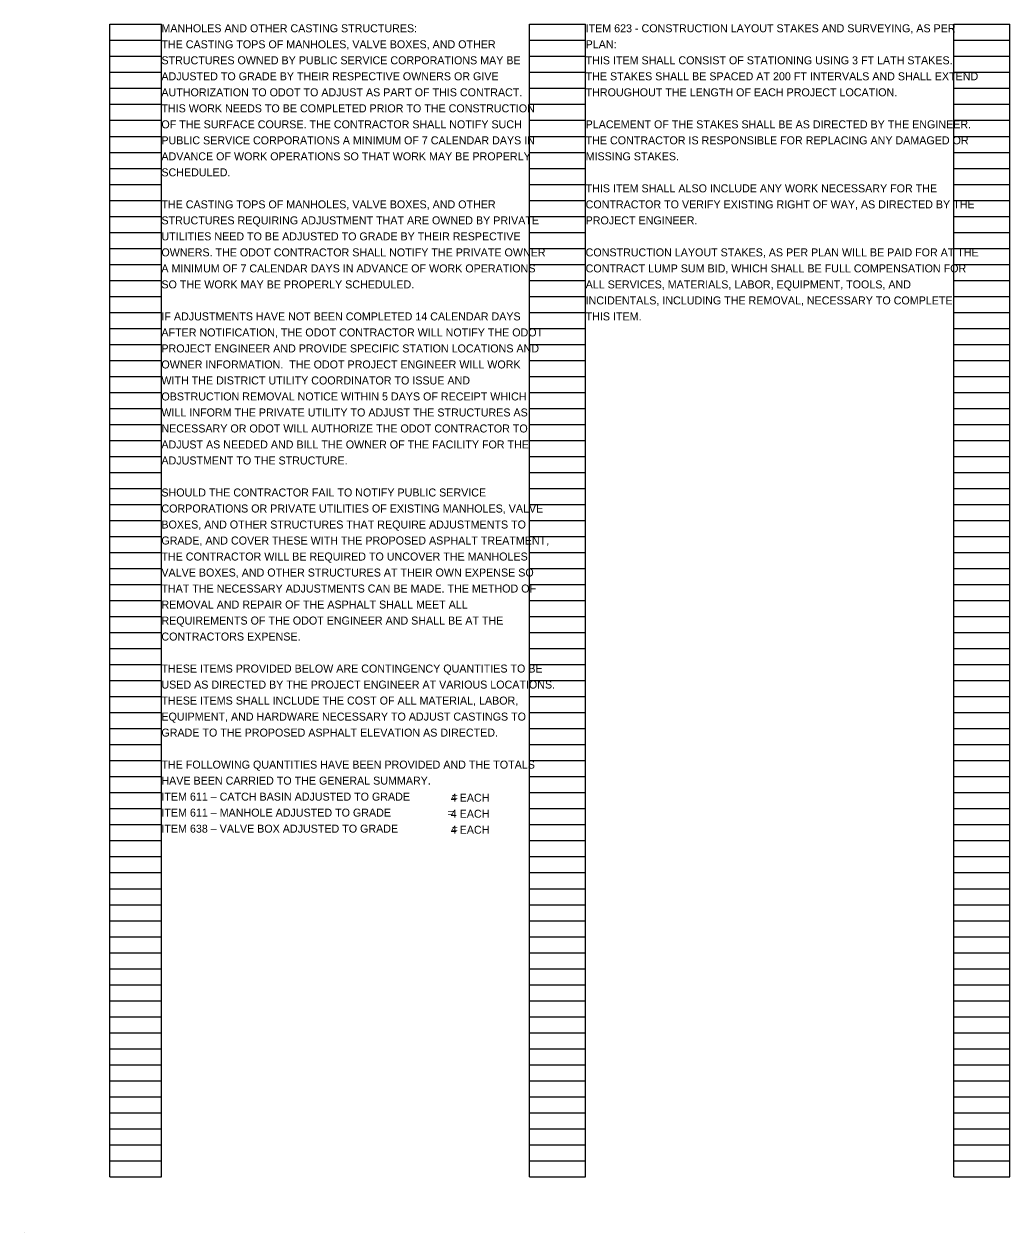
# Model space of a CAD drawing. Extents: x 28776.5 to 28808.5, y 9178.8 to 9230.7.
# Drawn here: x 28776.53 to 28793.77, y 9178.8 to 9199.94 of the extents above; entities that cross this region are included whole.
import ezdxf

# ---------------------------------------------------------------- set-up
doc = ezdxf.new("R2010")
doc.units = 0
doc.layers.add('SH_Data', color=7, linetype='Continuous')
doc.layers.add('SH_Text', color=7, linetype='Continuous')

msp = doc.modelspace()

# ---------------------------------------------------------------- linework, layer by layer
at = {"layer": 'SH_Data'}
for p, q in [((28778.029, 9179.776), (28778.029, 9199.936)), ((28778.029, 9199.936), (28778.929, 9199.936)), ((28778.929, 9179.776), (28778.929, 9199.936)), ((28785.369, 9179.776), (28785.369, 9199.936)), ((28785.369, 9199.936), (28786.349, 9199.936)), ((28786.349, 9179.776), (28786.349, 9199.936)), ((28792.789, 9179.776), (28792.789, 9199.936)), ((28792.789, 9199.936), (28793.769, 9199.936)), ((28793.769, 9179.776), (28793.769, 9199.936)), ((28778.029, 9199.656), (28778.929, 9199.656)), ((28785.369, 9199.656), (28786.349, 9199.656)), ((28792.789, 9199.656), (28793.769, 9199.656)), ((28778.029, 9199.376), (28778.929, 9199.376)), ((28785.369, 9199.376), (28786.349, 9199.376)), ((28792.789, 9199.376), (28793.769, 9199.376)), ((28778.029, 9199.096), (28778.929, 9199.096)), ((28785.369, 9199.096), (28786.349, 9199.096)), ((28792.789, 9199.096), (28793.769, 9199.096)), ((28778.029, 9198.816), (28778.929, 9198.816)), ((28785.369, 9198.816), (28786.349, 9198.816)), ((28792.789, 9198.816), (28793.769, 9198.816)), ((28778.029, 9198.536), (28778.929, 9198.536)), ((28785.369, 9198.536), (28786.349, 9198.536)), ((28792.789, 9198.536), (28793.769, 9198.536)), ((28778.029, 9198.256), (28778.929, 9198.256)), ((28785.369, 9198.256), (28786.349, 9198.256)), ((28792.789, 9198.256), (28793.769, 9198.256)), ((28778.029, 9197.976), (28778.929, 9197.976)), ((28785.369, 9197.976), (28786.349, 9197.976)), ((28792.789, 9197.976), (28793.769, 9197.976)), ((28778.029, 9197.696), (28778.929, 9197.696)), ((28785.369, 9197.696), (28786.349, 9197.696)), ((28792.789, 9197.696), (28793.769, 9197.696)), ((28778.029, 9197.416), (28778.929, 9197.416)), ((28785.369, 9197.416), (28786.349, 9197.416)), ((28792.789, 9197.416), (28793.769, 9197.416)), ((28778.029, 9197.136), (28778.929, 9197.136)), ((28785.369, 9197.136), (28786.349, 9197.136)), ((28792.789, 9197.136), (28793.769, 9197.136)), ((28778.029, 9196.856), (28778.929, 9196.856)), ((28785.369, 9196.856), (28786.349, 9196.856)), ((28792.789, 9196.856), (28793.769, 9196.856)), ((28778.029, 9196.576), (28778.929, 9196.576)), ((28785.369, 9196.576), (28786.349, 9196.576)), ((28792.789, 9196.576), (28793.769, 9196.576)), ((28778.029, 9196.296), (28778.929, 9196.296)), ((28785.369, 9196.296), (28786.349, 9196.296)), ((28792.789, 9196.296), (28793.769, 9196.296)), ((28778.029, 9196.016), (28778.929, 9196.016)), ((28785.369, 9196.016), (28786.349, 9196.016)), ((28792.789, 9196.016), (28793.769, 9196.016)), ((28778.029, 9195.736), (28778.929, 9195.736)), ((28785.369, 9195.736), (28786.349, 9195.736)), ((28792.789, 9195.736), (28793.769, 9195.736)), ((28778.029, 9195.456), (28778.929, 9195.456)), ((28785.369, 9195.456), (28786.349, 9195.456)), ((28792.789, 9195.456), (28793.769, 9195.456)), ((28778.029, 9195.176), (28778.929, 9195.176)), ((28785.369, 9195.176), (28786.349, 9195.176)), ((28792.789, 9195.176), (28793.769, 9195.176)), ((28778.029, 9194.896), (28778.929, 9194.896)), ((28785.369, 9194.896), (28786.349, 9194.896)), ((28792.789, 9194.896), (28793.769, 9194.896)), ((28778.029, 9194.616), (28778.929, 9194.616)), ((28785.369, 9194.616), (28786.349, 9194.616)), ((28792.789, 9194.616), (28793.769, 9194.616)), ((28778.029, 9194.336), (28778.929, 9194.336)), ((28785.369, 9194.336), (28786.349, 9194.336)), ((28792.789, 9194.336), (28793.769, 9194.336)), ((28778.029, 9194.056), (28778.929, 9194.056)), ((28785.369, 9194.056), (28786.349, 9194.056)), ((28792.789, 9194.056), (28793.769, 9194.056)), ((28778.029, 9193.776), (28778.929, 9193.776)), ((28785.369, 9193.776), (28786.349, 9193.776)), ((28792.789, 9193.776), (28793.769, 9193.776)), ((28778.029, 9193.496), (28778.929, 9193.496)), ((28785.369, 9193.496), (28786.349, 9193.496)), ((28792.789, 9193.496), (28793.769, 9193.496)), ((28778.029, 9193.216), (28778.929, 9193.216)), ((28785.369, 9193.216), (28786.349, 9193.216)), ((28792.789, 9193.216), (28793.769, 9193.216)), ((28778.029, 9192.936), (28778.929, 9192.936)), ((28785.369, 9192.936), (28786.349, 9192.936)), ((28792.789, 9192.936), (28793.769, 9192.936)), ((28778.029, 9192.656), (28778.929, 9192.656)), ((28785.369, 9192.656), (28786.349, 9192.656)), ((28792.789, 9192.656), (28793.769, 9192.656)), ((28778.029, 9192.376), (28778.929, 9192.376)), ((28785.369, 9192.376), (28786.349, 9192.376)), ((28792.789, 9192.376), (28793.769, 9192.376)), ((28778.029, 9192.096), (28778.929, 9192.096)), ((28785.369, 9192.096), (28786.349, 9192.096)), ((28792.789, 9192.096), (28793.769, 9192.096)), ((28778.029, 9191.816), (28778.929, 9191.816)), ((28785.369, 9191.816), (28786.349, 9191.816)), ((28792.789, 9191.816), (28793.769, 9191.816)), ((28778.029, 9191.536), (28778.929, 9191.536)), ((28785.369, 9191.536), (28786.349, 9191.536)), ((28792.789, 9191.536), (28793.769, 9191.536)), ((28778.029, 9191.256), (28778.929, 9191.256)), ((28785.369, 9191.256), (28786.349, 9191.256)), ((28792.789, 9191.256), (28793.769, 9191.256)), ((28778.029, 9190.976), (28778.929, 9190.976)), ((28785.369, 9190.976), (28786.349, 9190.976)), ((28792.789, 9190.976), (28793.769, 9190.976)), ((28778.029, 9190.696), (28778.929, 9190.696)), ((28785.369, 9190.696), (28786.349, 9190.696)), ((28792.789, 9190.696), (28793.769, 9190.696)), ((28778.029, 9190.416), (28778.929, 9190.416)), ((28785.369, 9190.416), (28786.349, 9190.416)), ((28792.789, 9190.416), (28793.769, 9190.416)), ((28778.029, 9190.136), (28778.929, 9190.136)), ((28785.369, 9190.136), (28786.349, 9190.136)), ((28792.789, 9190.136), (28793.769, 9190.136)), ((28778.029, 9189.856), (28778.929, 9189.856)), ((28785.369, 9189.856), (28786.349, 9189.856)), ((28792.789, 9189.856), (28793.769, 9189.856)), ((28778.029, 9189.576), (28778.929, 9189.576)), ((28785.369, 9189.576), (28786.349, 9189.576)), ((28792.789, 9189.576), (28793.769, 9189.576)), ((28778.029, 9189.296), (28778.929, 9189.296)), ((28785.369, 9189.296), (28786.349, 9189.296)), ((28792.789, 9189.296), (28793.769, 9189.296)), ((28778.029, 9189.016), (28778.929, 9189.016)), ((28785.369, 9189.016), (28786.349, 9189.016)), ((28792.789, 9189.016), (28793.769, 9189.016)), ((28778.029, 9188.736), (28778.929, 9188.736)), ((28785.369, 9188.736), (28786.349, 9188.736)), ((28792.789, 9188.736), (28793.769, 9188.736)), ((28778.029, 9188.456), (28778.929, 9188.456)), ((28785.369, 9188.456), (28786.349, 9188.456)), ((28792.789, 9188.456), (28793.769, 9188.456)), ((28778.029, 9188.176), (28778.929, 9188.176)), ((28785.369, 9188.176), (28786.349, 9188.176)), ((28792.789, 9188.176), (28793.769, 9188.176)), ((28778.029, 9187.896), (28778.929, 9187.896)), ((28785.369, 9187.896), (28786.349, 9187.896)), ((28792.789, 9187.896), (28793.769, 9187.896)), ((28778.029, 9187.616), (28778.929, 9187.616)), ((28785.369, 9187.616), (28786.349, 9187.616)), ((28792.789, 9187.616), (28793.769, 9187.616)), ((28778.029, 9187.336), (28778.929, 9187.336)), ((28785.369, 9187.336), (28786.349, 9187.336)), ((28792.789, 9187.336), (28793.769, 9187.336)), ((28778.029, 9187.056), (28778.929, 9187.056)), ((28785.369, 9187.056), (28786.349, 9187.056)), ((28792.789, 9187.056), (28793.769, 9187.056)), ((28778.029, 9186.776), (28778.929, 9186.776)), ((28785.369, 9186.776), (28786.349, 9186.776)), ((28792.789, 9186.776), (28793.769, 9186.776)), ((28778.029, 9186.496), (28778.929, 9186.496)), ((28785.369, 9186.496), (28786.349, 9186.496)), ((28792.789, 9186.496), (28793.769, 9186.496)), ((28778.029, 9186.216), (28778.929, 9186.216)), ((28785.369, 9186.216), (28786.349, 9186.216)), ((28792.789, 9186.216), (28793.769, 9186.216)), ((28778.029, 9185.936), (28778.929, 9185.936)), ((28785.369, 9185.936), (28786.349, 9185.936)), ((28792.789, 9185.936), (28793.769, 9185.936)), ((28778.029, 9185.656), (28778.929, 9185.656)), ((28785.369, 9185.656), (28786.349, 9185.656)), ((28792.789, 9185.656), (28793.769, 9185.656)), ((28778.029, 9185.376), (28778.929, 9185.376)), ((28785.369, 9185.376), (28786.349, 9185.376)), ((28792.789, 9185.376), (28793.769, 9185.376)), ((28778.029, 9185.096), (28778.929, 9185.096)), ((28785.369, 9185.096), (28786.349, 9185.096)), ((28792.789, 9185.096), (28793.769, 9185.096)), ((28778.029, 9184.816), (28778.929, 9184.816)), ((28785.369, 9184.816), (28786.349, 9184.816)), ((28792.789, 9184.816), (28793.769, 9184.816)), ((28778.029, 9184.536), (28778.929, 9184.536)), ((28785.369, 9184.536), (28786.349, 9184.536)), ((28792.789, 9184.536), (28793.769, 9184.536)), ((28778.029, 9184.256), (28778.929, 9184.256)), ((28785.369, 9184.256), (28786.349, 9184.256)), ((28792.789, 9184.256), (28793.769, 9184.256)), ((28778.029, 9183.976), (28778.929, 9183.976)), ((28785.369, 9183.976), (28786.349, 9183.976)), ((28792.789, 9183.976), (28793.769, 9183.976)), ((28778.029, 9183.696), (28778.929, 9183.696)), ((28785.369, 9183.696), (28786.349, 9183.696)), ((28792.789, 9183.696), (28793.769, 9183.696)), ((28778.029, 9183.416), (28778.929, 9183.416)), ((28785.369, 9183.416), (28786.349, 9183.416)), ((28792.789, 9183.416), (28793.769, 9183.416)), ((28778.029, 9183.136), (28778.929, 9183.136)), ((28785.369, 9183.136), (28786.349, 9183.136)), ((28792.789, 9183.136), (28793.769, 9183.136)), ((28778.029, 9182.856), (28778.929, 9182.856)), ((28785.369, 9182.856), (28786.349, 9182.856)), ((28792.789, 9182.856), (28793.769, 9182.856)), ((28778.029, 9182.576), (28778.929, 9182.576)), ((28785.369, 9182.576), (28786.349, 9182.576)), ((28792.789, 9182.576), (28793.769, 9182.576)), ((28778.029, 9182.296), (28778.929, 9182.296)), ((28785.369, 9182.296), (28786.349, 9182.296)), ((28792.789, 9182.296), (28793.769, 9182.296)), ((28778.029, 9182.016), (28778.929, 9182.016)), ((28785.369, 9182.016), (28786.349, 9182.016)), ((28792.789, 9182.016), (28793.769, 9182.016)), ((28778.029, 9181.736), (28778.929, 9181.736)), ((28785.369, 9181.736), (28786.349, 9181.736)), ((28792.789, 9181.736), (28793.769, 9181.736)), ((28778.029, 9181.456), (28778.929, 9181.456)), ((28785.369, 9181.456), (28786.349, 9181.456)), ((28792.789, 9181.456), (28793.769, 9181.456)), ((28778.029, 9181.176), (28778.929, 9181.176)), ((28785.369, 9181.176), (28786.349, 9181.176)), ((28792.789, 9181.176), (28793.769, 9181.176)), ((28778.029, 9180.896), (28778.929, 9180.896)), ((28785.369, 9180.896), (28786.349, 9180.896)), ((28792.789, 9180.896), (28793.769, 9180.896)), ((28778.029, 9180.616), (28778.929, 9180.616)), ((28785.369, 9180.616), (28786.349, 9180.616)), ((28792.789, 9180.616), (28793.769, 9180.616)), ((28778.029, 9180.336), (28778.929, 9180.336)), ((28785.369, 9180.336), (28786.349, 9180.336)), ((28792.789, 9180.336), (28793.769, 9180.336)), ((28778.029, 9180.056), (28778.929, 9180.056)), ((28785.369, 9180.056), (28786.349, 9180.056)), ((28792.789, 9180.056), (28793.769, 9180.056)), ((28778.029, 9179.776), (28778.929, 9179.776)), ((28785.369, 9179.776), (28786.349, 9179.776)), ((28792.789, 9179.776), (28793.769, 9179.776)), ((28776.529, 9178.796), (28776.529, 9178.796))]:
    msp.add_line(p, q, dxfattribs=at)

# ---------------------------------------------------------------- texts
for p in [(28783.99, 9186.337), (28783.99, 9186.057), (28783.99, 9185.777)]:
    msp.add_text('4 EACH', height=0.14, dxfattribs=at).set_placement(p)
at = {"layer": 'SH_Text'}
for s, p in [('MANHOLES AND OTHER CASTING STRUCTURES:', (28778.929, 9199.796)), ('ITEM 623 - CONSTRUCTION LAYOUT STAKES AND SURVEYING, AS PER ', (28786.349, 9199.796)), ('THE CASTING TOPS OF MANHOLES, VALVE BOXES, AND OTHER ', (28778.929, 9199.516)), ('PLAN:', (28786.349, 9199.516)), ('STRUCTURES OWNED BY PUBLIC SERVICE CORPORATIONS MAY BE ', (28778.929, 9199.236)), ('THIS ITEM SHALL CONSIST OF STATIONING USING 3 FT LATH STAKES. ', (28786.349, 9199.236)), ('ADJUSTED TO GRADE BY THEIR RESPECTIVE OWNERS OR GIVE ', (28778.929, 9198.956)), ('THE STAKES SHALL BE SPACED AT 200 FT INTERVALS AND SHALL EXTEND ', (28786.349, 9198.956)), ('AUTHORIZATION TO ODOT TO ADJUST AS PART OF THIS CONTRACT.  ', (28778.929, 9198.676)), ('THROUGHOUT THE LENGTH OF EACH PROJECT LOCATION.', (28786.349, 9198.676)), ('THIS WORK NEEDS TO BE COMPLETED PRIOR TO THE CONSTRUCTION ', (28778.929, 9198.396)), ('OF THE SURFACE COURSE. THE CONTRACTOR SHALL NOTIFY SUCH ', (28778.929, 9198.116)), ('PLACEMENT OF THE STAKES SHALL BE AS DIRECTED BY THE ENGINEER. ', (28786.349, 9198.116)), ('PUBLIC SERVICE CORPORATIONS A MINIMUM OF 7 CALENDAR DAYS IN ', (28778.929, 9197.836)), ('THE CONTRACTOR IS RESPONSIBLE FOR REPLACING ANY DAMAGED OR ', (28786.349, 9197.836)), ('ADVANCE OF WORK OPERATIONS SO THAT WORK MAY BE PROPERLY ', (28778.929, 9197.556)), ('MISSING STAKES.', (28786.349, 9197.556)), ('SCHEDULED.', (28778.929, 9197.276)), ('THIS ITEM SHALL ALSO INCLUDE ANY WORK NECESSARY FOR THE ', (28786.349, 9196.996)), ('THE CASTING TOPS OF MANHOLES, VALVE BOXES, AND OTHER ', (28778.929, 9196.716)), ('CONTRACTOR TO VERIFY EXISTING RIGHT OF WAY, AS DIRECTED BY THE ', (28786.349, 9196.716)), ('STRUCTURES REQUIRING ADJUSTMENT THAT ARE OWNED BY PRIVATE ', (28778.929, 9196.436)), ('PROJECT ENGINEER. ', (28786.349, 9196.436)), ('UTILITIES NEED TO BE ADJUSTED TO GRADE BY THEIR RESPECTIVE ', (28778.929, 9196.156)), ('OWNERS. THE ODOT CONTRACTOR SHALL NOTIFY THE PRIVATE OWNER ', (28778.929, 9195.876)), ('CONSTRUCTION LAYOUT STAKES, AS PER PLAN WILL BE PAID FOR AT THE ', (28786.349, 9195.876)), ('A MINIMUM OF 7 CALENDAR DAYS IN ADVANCE OF WORK OPERATIONS ', (28778.929, 9195.596)), ('CONTRACT LUMP SUM BID, WHICH SHALL BE FULL COMPENSATION FOR ', (28786.349, 9195.596)), ('SO THE WORK MAY BE PROPERLY SCHEDULED.', (28778.929, 9195.316)), ('ALL SERVICES, MATERIALS, LABOR, EQUIPMENT, TOOLS, AND ', (28786.349, 9195.316)), ('INCIDENTALS, INCLUDING THE REMOVAL, NECESSARY TO COMPLETE ', (28786.349, 9195.036)), ('IF ADJUSTMENTS HAVE NOT BEEN COMPLETED 14 CALENDAR DAYS ', (28778.929, 9194.756)), ('THIS ITEM.', (28786.349, 9194.756)), ('AFTER NOTIFICATION, THE ODOT CONTRACTOR WILL NOTIFY THE ODOT ', (28778.929, 9194.476)), ('PROJECT ENGINEER AND PROVIDE SPECIFIC STATION LOCATIONS AND ', (28778.929, 9194.196)), ('OWNER INFORMATION.  THE ODOT PROJECT ENGINEER WILL WORK ', (28778.929, 9193.916)), ('WITH THE DISTRICT UTILITY COORDINATOR TO ISSUE AND ', (28778.929, 9193.636)), ('OBSTRUCTION REMOVAL NOTICE WITHIN 5 DAYS OF RECEIPT WHICH ', (28778.929, 9193.356)), ('WILL INFORM THE PRIVATE UTILITY TO ADJUST THE STRUCTURES AS ', (28778.929, 9193.076)), ('NECESSARY OR ODOT WILL AUTHORIZE THE ODOT CONTRACTOR TO ', (28778.929, 9192.796)), ('ADJUST AS NEEDED AND BILL THE OWNER OF THE FACILITY FOR THE ', (28778.929, 9192.516)), ('ADJUSTMENT TO THE STRUCTURE.', (28778.929, 9192.236)), ('SHOULD THE CONTRACTOR FAIL TO NOTIFY PUBLIC SERVICE ', (28778.929, 9191.676)), ('CORPORATIONS OR PRIVATE UTILITIES OF EXISTING MANHOLES, VALVE ', (28778.929, 9191.396)), ('BOXES, AND OTHER STRUCTURES THAT REQUIRE ADJUSTMENTS TO ', (28778.929, 9191.116)), ('GRADE, AND COVER THESE WITH THE PROPOSED ASPHALT TREATMENT, ', (28778.929, 9190.836)), ('THE CONTRACTOR WILL BE REQUIRED TO UNCOVER THE MANHOLES, ', (28778.929, 9190.556)), ('VALVE BOXES, AND OTHER STRUCTURES AT THEIR OWN EXPENSE SO ', (28778.929, 9190.276)), ('THAT THE NECESSARY ADJUSTMENTS CAN BE MADE. THE METHOD OF ', (28778.929, 9189.996)), ('REMOVAL AND REPAIR OF THE ASPHALT SHALL MEET ALL ', (28778.929, 9189.716)), ('REQUIREMENTS OF THE ODOT ENGINEER AND SHALL BE AT THE ', (28778.929, 9189.436)), ('CONTRACTORS EXPENSE.', (28778.929, 9189.156)), ('THESE ITEMS PROVIDED BELOW ARE CONTINGENCY QUANTITIES TO BE ', (28778.929, 9188.596)), ('USED AS DIRECTED BY THE PROJECT ENGINEER AT VARIOUS LOCATIONS. ', (28778.929, 9188.316)), ('THESE ITEMS SHALL INCLUDE THE COST OF ALL MATERIAL, LABOR, ', (28778.929, 9188.036)), ('EQUIPMENT, AND HARDWARE NECESSARY TO ADJUST CASTINGS TO ', (28778.929, 9187.756)), ('GRADE TO THE PROPOSED ASPHALT ELEVATION AS DIRECTED.', (28778.929, 9187.476)), ('THE FOLLOWING QUANTITIES HAVE BEEN PROVIDED AND THE TOTALS ', (28778.929, 9186.916)), ('HAVE BEEN CARRIED TO THE GENERAL SUMMARY.', (28778.929, 9186.636)), ('ITEM 611 – CATCH BASIN ADJUSTED TO GRADE              =    ', (28778.929, 9186.356)), ('ITEM 611 – MANHOLE ADJUSTED TO GRADE                   =     ', (28778.929, 9186.076)), ('ITEM 638 – VALVE BOX ADJUSTED TO GRADE                  =    ', (28778.929, 9185.796))]:
    msp.add_text(s, height=0.14, dxfattribs=at).set_placement(p)

doc.saveas('drawing.dxf')
